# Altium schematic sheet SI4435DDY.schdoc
size 127 x 101 mm
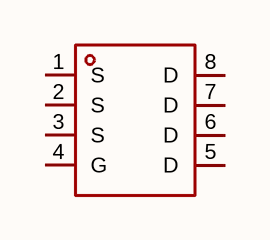
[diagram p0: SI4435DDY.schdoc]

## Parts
Q?  si4435ddy  [SOP-8_L4.9-W3.9-P1.27-LS6.0-BL]  (value not drawn)

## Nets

Not connected (* = marked no-connect by the designer): Q? 1(S) 2(S) 3(S) 4(G) 5(D) 6(D) 7(D) 8(D)

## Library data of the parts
Q? = si4435ddy: 数量:1个P沟道;漏源电压(Vdss):30V;连续漏极电流(Id):12A;导通电阻(RDS(on)):9.5mΩ@10V；14mΩ@4.5V;耗散功率(Pd):3W;阈值电压(Vgs(th)):1.5V;; Manufacturer: TECH PUBLIC(台舟); AddInBom: yes; ModelId: 75c24a7891ee4dd6bdac16a7163ff87e; ModelName: SOP-8_L4.9-W3.9-P1.27-LS6.0-BL-1; ModelTransform: 192.913,236.22,0,0,0,0,-0.393,2.749,0; Number: 1个P沟道; Drain to Source Voltage: 30V; Current - Continuous Drain(Id): 12A; Pd - Power Dissipation: 3W; Gate Threshold Voltage (Vgs(th)): 1.5V; Gate Charge(Qg): 25nC@10V; Input Capacitance(Ciss): 1.2nF; Reverse Transfer Capacitance (Crss@Vds): 150pF; Type: P沟道; Output Capacitance(Coss): 200pF; Vgs: ±20V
